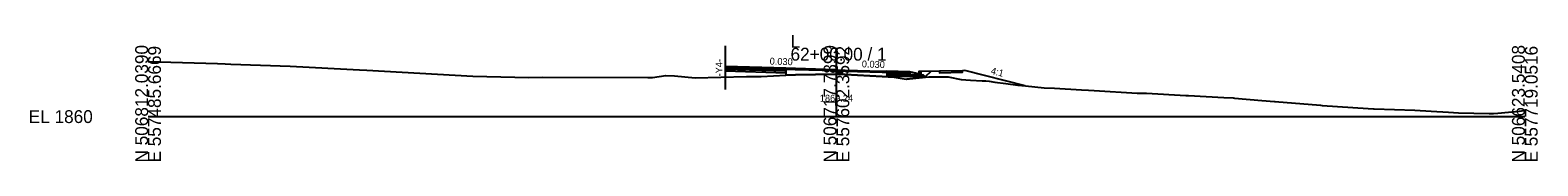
# Model space of a CAD drawing. Extents: x -26 to 4603, y -10 to 4703.
# Drawn here: x 2474.3 to 2802.8, y 875.3 to 902.8 of the extents above; entities that cross this region are included whole.
import ezdxf

# ---------------------------------------------------------------- set-up
doc = ezdxf.new("R2010")
doc.units = 0
for name, color, linetype in [('Default', 7, 'Continuous'), ('Exist Cross Section Cell', 7, 'Continuous'), ('Exist XS Ground Line', 7, 'Continuous'), ('Prop CMT Pvmt Course 1', 7, 'Continuous'), ('Prop CMT Pvmt Course 2', 7, 'Continuous'), ('Prop CMT Pvmt Course 3', 7, 'Continuous'), ('Prop CMT Pvmt Milling', 7, 'Continuous'), ('Prop CMT Shear Line', 7, 'Continuous'), ('Prop CMT Shld Paved Course 2', 7, 'Continuous'), ('Prop CMT Subgrade Earthwork', 7, 'Continuous'), ('Prop Conc 4in Sidewalk', 7, 'Continuous'), ('Prop Conc Curb and Gutter', 7, 'Continuous'), ('Prop Corridor Mesh Bottom', 7, 'Continuous'), ('Prop XS Finish Grade', 7, 'Continuous'), ('Prop XS Label Text', 7, 'Continuous'), ('Prop XS Shear Point Element', 7, 'Continuous'), ('Prop XS Shear Point Label', 7, 'Continuous'), ('Prop XS SS Elevation Text', 7, 'Continuous')]:
    doc.layers.add(name, color=color, linetype=linetype)

msp = doc.modelspace()

# ---------------------------------------------------------------- linework, layer by layer
at = {"layer": 'Exist Cross Section Cell'}
for p, q in [((2650, 885), (2650, 900)), ((2500, 885), (2650, 885)), ((2650, 885), (2800, 885))]:
    msp.add_line(p, q, dxfattribs=at)
at = {"layer": 'Exist XS Ground Line'}
msp.add_lwpolyline([(2500, 897.04), (2502.43, 896.94), (2515.15, 896.57), (2516.79, 896.52), (2518.01, 896.46), (2531, 895.97), (2546.08, 895.21), (2547.65, 895.14), (2570.79, 893.79), (2582.94, 893.55), (2585.97, 893.59), (2608.87, 893.55), (2609.92, 893.54), (2612.86, 893.99), (2614.68, 893.91), (2619.23, 893.42), (2630.41, 893.72), (2633.6, 893.77), (2638.95, 894.02), (2641.1, 894.07), (2649.79, 894.24), (2651.89, 894.15), (2659.97, 893.73), (2662.55, 893.57), (2665.19, 893.19), (2665.4, 893.25), (2665.91, 893.21), (2670.15, 893.66), (2670.43, 893.66), (2674.08, 893.67), (2674.3, 893.66), (2674.37, 893.65), (2677.19, 893.07), (2679.2, 892.96), (2681.76, 892.81), (2682.57, 892.77), (2683.31, 892.71), (2684.53, 892.5), (2686.92, 892.19), (2689.54, 891.86), (2691.22, 891.71), (2695.25, 891.28), (2697.55, 891.22), (2703.4, 890.83), (2704.96, 890.73), (2706.17, 890.69), (2715.5, 890.12), (2716.58, 890.12), (2717.56, 890.11), (2726.16, 889.62), (2726.69, 889.6), (2734.4, 889.15), (2736.48, 889.06), (2736.72, 889.03), (2742.66, 888.53), (2745.49, 888.29), (2745.52, 888.28), (2745.54, 888.28), (2745.56, 888.27), (2755.45, 887.51), (2755.83, 887.45), (2765.85, 886.77), (2767.05, 886.69), (2767.19, 886.68), (2776.01, 886.38), (2779.61, 886.19), (2783.4, 885.99), (2785.52, 885.84), (2792.26, 885.64), (2793.02, 885.68), (2793.19, 885.7), (2794.1, 885.78), (2798.74, 886.21), (2799.78, 886.35), (2800, 886.37)], dxfattribs=at)
at = {"layer": 'Prop CMT Pvmt Course 1'}
for points in [[(2639, 895.53), (2625.83, 895.92), (2625.83, 895.92), (2625.83, 895.67), (2639, 895.28), (2639, 895.28), (2639, 895.53), (2639, 895.53), (2639, 895.53)], [(2649.79, 895.21), (2649.79, 895.21), (2641.1, 895.47), (2641.1, 895.47), (2639, 895.53), (2639, 895.53), (2639, 894.02), (2641.1, 894.07), (2641.1, 894.07), (2649.79, 894.24), (2649.79, 894.24), (2649.79, 894.24), (2650, 894.24), (2650, 895.2), (2650, 895.2), (2649.79, 895.21), (2649.79, 895.21)], [(2661, 894.87), (2661, 894.87), (2661, 894.87), (2661, 893.66), (2659.97, 893.73), (2659.97, 893.73), (2659.97, 893.73), (2651.89, 894.15), (2651.89, 894.15), (2650, 894.24), (2650, 895.2), (2650, 895.2), (2651.89, 895.14), (2651.89, 895.14), (2659.97, 894.9), (2659.97, 894.9), (2661, 894.87)], [(2661, 894.87), (2661, 894.87), (2661, 894.87), (2661, 894.62), (2661, 894.62), (2665.98, 894.47), (2665.98, 894.72), (2665.98, 894.72), (2661, 894.87)]]:
    msp.add_lwpolyline(points, dxfattribs=at)
at = {"layer": 'Prop CMT Pvmt Course 2'}
for points in [[(2639, 895.28), (2625.83, 895.67), (2625.83, 895.67), (2625.83, 895.34), (2639, 894.95), (2639, 894.95), (2639, 895.28), (2639, 895.28), (2639, 895.28)], [(2661, 894.62), (2661, 894.62), (2661, 894.62), (2661, 894.29), (2661, 894.29), (2665.98, 894.14), (2665.98, 894.47), (2665.98, 894.47), (2661, 894.62)]]:
    msp.add_lwpolyline(points, dxfattribs=at)
at = {"layer": 'Prop CMT Pvmt Course 3'}
for points in [[(2639, 894.95), (2625.83, 895.34), (2625.83, 895.34), (2625.83, 894.97), (2639, 894.57), (2639, 894.57), (2639, 894.95), (2639, 894.95), (2639, 894.95)], [(2661, 894.29), (2661, 894.29), (2661, 894.29), (2661, 893.91), (2661, 893.91), (2665.98, 893.76), (2665.98, 894.14), (2665.98, 894.14), (2661, 894.29)], [(2665.98, 894.14), (2665.98, 894.14), (2665.98, 894.14), (2665.98, 893.76), (2665.98, 893.76), (2669.37, 893.66), (2668.98, 894.05), (2668.98, 894.05), (2665.98, 894.14)]]:
    msp.add_lwpolyline(points, dxfattribs=at)
at = {"layer": 'Prop CMT Pvmt Milling'}
for points in [[(2650, 894.24), (2649.79, 894.24), (2649.79, 894.24), (2649.79, 894.24), (2641.1, 894.07), (2641.1, 894.07), (2639, 894.02)], [(2661, 893.66), (2659.97, 893.73), (2659.97, 893.73), (2659.97, 893.73), (2651.89, 894.15), (2651.89, 894.15), (2650, 894.24)]]:
    msp.add_lwpolyline(points, dxfattribs=at)
at = {"layer": 'Prop CMT Shld Paved Course 2'}
for points in [[(2649.79, 894.96), (2649.79, 894.96), (2641.1, 895.22), (2641.1, 895.22), (2639, 895.28), (2639, 895.28), (2639, 894.02), (2641.1, 894.07), (2641.1, 894.07), (2649.79, 894.24), (2649.79, 894.24), (2649.79, 894.24), (2650, 894.24), (2650, 894.95), (2650, 894.95), (2649.79, 894.96), (2649.79, 894.96)], [(2661, 894.62), (2661, 894.62), (2661, 894.62), (2661, 893.66), (2659.97, 893.73), (2659.97, 893.73), (2659.97, 893.73), (2651.89, 894.15), (2651.89, 894.15), (2650, 894.24), (2650, 894.95), (2650, 894.95), (2651.89, 894.89), (2651.89, 894.89), (2659.97, 894.65), (2659.97, 894.65), (2661, 894.62)]]:
    msp.add_lwpolyline(points, dxfattribs=at)
at = {"layer": 'Prop CMT Subgrade Earthwork'}
for points in [[(2625.83, 894.97), (2639, 894.57)], [(2669.37, 893.66), (2661, 893.91), (2661, 893.91)], [(2670.57, 894.86), (2670.57, 894.86), (2669.37, 893.66)]]:
    msp.add_lwpolyline(points, dxfattribs=at)
at = {"layer": 'Prop Conc 4in Sidewalk'}
msp.add_lwpolyline([(2677.48, 895), (2672.48, 894.9), (2672.48, 894.9), (2672.47, 894.57), (2677.49, 894.67), (2677.49, 894.67), (2677.48, 895), (2677.48, 895), (2677.48, 895)], dxfattribs=at)
at = {"layer": 'Prop Conc Curb and Gutter'}
msp.add_lwpolyline([(2665.98, 894.72), (2665.98, 894.72), (2665.98, 894.72), (2665.98, 894.14), (2665.98, 894.14), (2668.48, 894.06), (2668.48, 894.82), (2668.48, 894.82), (2667.98, 894.82), (2667.98, 894.82), (2667.98, 894.82), (2667.98, 894.32), (2665.98, 894.72)], dxfattribs=at)
at = {"layer": 'Prop Corridor Mesh Bottom'}
msp.add_lwpolyline([(2665.98, 894.72), (2665.98, 894.47)], dxfattribs=at)
at = {"layer": 'Prop XS Finish Grade'}
for points in [[(2672.48, 894.9), (2672.48, 894.9), (2668.48, 894.82)], [(2677.98, 895.01), (2677.98, 895.01), (2677.48, 895)], [(2691.15, 891.72), (2677.98, 895.01), (2677.98, 895.01)]]:
    msp.add_lwpolyline(points, dxfattribs=at)
at = {"layer": 'Prop XS Shear Point Element'}
msp.add_line((2625.83, 890.91), (2625.83, 900.4), dxfattribs=at)

# ---------------------------------------------------------------- texts
at = {"layer": 'Default'}
msp.add_text('-', height=0.0001, dxfattribs=at).set_placement((2500, 885))
at = {"layer": 'Exist Cross Section Cell'}
for s, p in [('N 506812.0390', (2500, 875)), ('E 557485.6669', (2502.8, 875)), ('N 506717.7899', (2650, 875)), ('E 557602.3592', (2652.8, 875)), ('N 506623.5408', (2800, 875)), ('E 557719.0516', (2802.8, 875))]:
    msp.add_text(s, height=2.8, rotation=90, dxfattribs=at).set_placement(p)
for s, p in [('L', (2640, 900)), ('62+00.00 / 1', (2640, 897.2)), ('EL 1860', (2474, 883.6))]:
    msp.add_text(s, height=2.8, dxfattribs=at).set_placement(p)
at = {"layer": 'Prop CMT Shear Line'}
for p in [(2625.83, 895.92), (2650, 895.2), (2665.98, 894.72), (2665.98, 894.72), (2667.98, 894.32), (2672.48, 894.9), (2677.48, 895), (2677.98, 895.01), (2691.15, 891.72)]:
    msp.add_text('X', height=0.0025, dxfattribs=at).set_placement(p)
at = {"layer": 'Prop XS Label Text'}
for s, rotation, p in [('0.030', 358.2816, (2635.43, 896.34)), ('0.030', 358.2816, (2655.51, 895.73)), ('4:1', 345.9638, (2683.54, 894.34))]:
    msp.add_text(s, height=1.5, rotation=rotation, dxfattribs=at).set_placement(p)
at = {"layer": 'Prop XS Shear Point Label'}
msp.add_text('-Y4-', height=1.5, rotation=90, dxfattribs=at).set_placement((2625.16, 893.77))
at = {"layer": 'Prop XS SS Elevation Text'}
msp.add_text('1869.24', height=1.5, dxfattribs=at).set_placement((2646.38, 888.26))

doc.saveas('drawing.dxf')
